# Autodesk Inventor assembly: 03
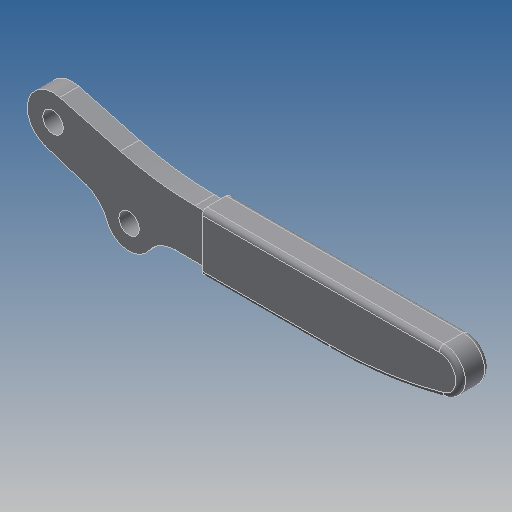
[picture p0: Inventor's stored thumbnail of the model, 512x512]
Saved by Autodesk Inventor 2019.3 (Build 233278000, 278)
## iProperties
Created: 2012-09
Part Number: 03
Material: Ogólny
Document SubType Name: Assembly
Designer: CADENGINEERING4
Author: CADENGINEERING4
Revision Number: ÈÎºÎ
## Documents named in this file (3)
- E:\STRONA\Horizontal toggle clamp\CH-202-F\03.iam
- E:\STRONA\Horizontal toggle clamp\CH-202-F\203-F-03.ipt
- E:\STRONA\Horizontal toggle clamp\CH-202-F\203-F-03-02.ipt
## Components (2 placed, 2 different names)
1. 203-F-03_16
2. 203-F-03-02_17
